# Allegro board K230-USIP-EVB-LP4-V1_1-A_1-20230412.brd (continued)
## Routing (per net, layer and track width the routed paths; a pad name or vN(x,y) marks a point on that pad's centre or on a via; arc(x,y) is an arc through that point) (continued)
GND3: length 4.6
  TOP w0.254: 56.26,30.61 55.73,31.13 U35.1
  TOP w0.305: 56.26,30.61 56.77,30.1 R290.1 R289.1
VBUS_IN: length 1.1
  TOP w0.381: R303.1 70.1,28.83
VDD0V8_KPU_EN: length 4.5
  TOP w0.305: U38.7 60.2,78.23 58.29,80.14 R301.1 C394.1
VDD_0V8: length 10.1
  ART06 w0.305: v1(60.07,35.56) 60.96,36.45 60.96,41.02 v1(59.56,42.42)
  BOTTOM w0.305: v1(60.07,35.56) R267.2 C320.1
VDD_1V1: length 4.4
  TOP w0.381: v1(45.97,28.19) 45.97,25.65
  BOTTOM w0.381: C328.1 R275.1 v1(45.97,28.19)
VDD_1V8: length 84.5
  TOP w0.203: U30.P5 43.16,116.48 v2(42.93,116.71) ; v1(66.57,119.25) 67,118.81 U25.2 ; U30.M4 U30.N4 U30.P3 44.32,116.44 v2(44.32,116.71) ; U34.2 59.11,100.13 v1(58.8,99.82) ; U30.C6 42.66,111.09 v2(42.52,111.23)
  TOP w0.254: U1.R13 25.65,78.38 v2(25.33,78.06) ; v2(32.47,79.36) 32.15,79.68 U1.E11 ; U1.R15 v2(25.33,77.41) ; U1.F13 v2(31.17,78.06) ; U1.H6 v2(30.53,82.61) ; U1.R11 v2(25.33,79.36)
  TOP w0.305: v1(66.19,114.43) R209.1 ; C315.1 v1(58.8,99.82) ; v1(66.57,119.25) C207.1 ; R280.2 v1(44.32,36.32)
  TOP w0.381: R238.1 R239.1 v1(44.58,124.46) ; R241.1 R240.1 v1(45.72,124.46) ; R200.1 v1(7.24,43.18) ; C206.2 4.57,53.21 J12.1 ; R199.1 v1(7.11,45.72) ; R207.1 v1(7.24,38.1) ; R206.1 v1(7.24,40.64) ; v1(49.4,77.09) 49.02,77.09 R129.1 ; R197.1 v1(7.11,50.8) ; R198.1 v1(7.11,48.26) ; J9.1 v1(32.7,119.89)
  BOTTOM w0.254: C258.1 42.04,109.98 C256.1 ; C258.1 41.15,111 R59.2 ; C258.1 42.29,111 v2(42.52,111.23) ; v2(44.32,116.71) R49.2 C257.1 43.18,116.46 v2(42.93,116.71)
  BOTTOM w0.305: R280.2 C323.1 45.21,38.35 47.5,40.64 v1(48.26,40.64) ; C242.2 32.7,120.21 v1(32.7,119.89) ; v1(58.8,99.82) 59.05,99.82 R146.1 ; 38.99,79.5 38.99,80.52 39.5,80.52 40.26,81.28 45.47,81.28 47.62,83.44 49.53,83.44 51.05,84.96 v1(51.05,89.15) ; v1(49.4,77.09) 49.4,82 52.83,85.43 52.83,88.52 v1(53.47,89.15) ; R48.2 C259.1 v1(36.7,109.73)
  BOTTOM w0.381: v1(71.5,50.67) R18.2 R20.2 ; R236.1 R237.1 v1(6.1,83.19) ; v3(41.4,128.27) R234.1 R235.1
  vias: v1(36.58,113.41) v1(36.58,112.14) v1(47.12,43.18) v1(47.12,41.91) v1(48.26,45.72) v1(48.26,44.45) v1(48.26,43.18) v1(48.26,41.91) v1(49.28,45.72) v1(49.28,44.45)
VDD_3V3: length 80.3
  TOP w0.203: U34.1 58.98,100.53 v1(58.8,100.71) ; U30.J10 41.14,113.78 v2(41.16,113.8) U30.K9 ; U36.2 53.01,110.56 v1(52.7,110.87) ; U30.E6 42.66,112.12 v2(42.79,112.25) 42.82,112.28 U30.F5 ; v1(67.71,119.25) 67.4,118.94 U25.1
  TOP w0.254: U1.M7 v2(27.28,82.61) ; U1.E10 v2(32.47,80.66)
  TOP w0.305: C316.2 v1(58.8,100.71) ; R284.2 v1(52.7,105.66) ; J3.57 46.76,128.93 ; v1(52.7,110.87) C367.2 ; v1(67.71,119.25) C208.2 ; J4.6 6.86,91.41 v1(6.6,91.15) 6.85,90.91 J4.5 ; J3.59 47.26,128.92
  TOP w0.381: v1(71.37,116.59) 71.63,116.84 R243.1 R242.1 ; J9.16 v1(32.7,105.79) ; R76.1 32.64,31.11 v1(32.64,25.15) ; R19.1 v1(18.16,18.16) ; TP10.1 v1(19.3,25.4) ; v1(71.75,87) 67.06,87 66.86,87.19 U4.4 ; R11.2 v1(60.96,115.82)
  BOTTOM w0.254: v2(41.16,113.8) 41.15,113.82 C18.1 ; 33.19,80.66 v2(32.47,80.66)
  BOTTOM w0.305: 27.18,85.09 C30.1 C81.1 ; C19.1 C22.1 42.8,112.27 v2(42.79,112.25) ; 35.81,80.14 C83.1 35.81,79.3 36.09,79.02 37.31,79.02 37.64,78.69 39.45,78.69 39.85,79.1 44.04,79.1 47.75,82.8 49.56,82.8 52.32,85.57 v1(52.32,92.33)
  BOTTOM w0.381: C260.1 32.7,105.35 v1(32.7,105.79) ; R190.1 v1(70.99,81.92) ; R245.2 v1(70.99,86.36) ; R194.1 v1(70.99,83.19) R189.1 ; R188.1 v1(70.99,85.09) ; R162.1 v1(70.99,87.63) ; R191.1 v1(71.25,91.44) ; R193.1 v1(70.99,88.9)
  vias: v1(12.32,24.38) v1(12.32,23.11) v1(12.32,21.84) v1(13.59,24.38) v1(13.59,23.11) v1(13.59,21.84) v1(19.3,24.13) v1(19.3,22.99) v1(19.3,21.84) v1(20.57,24.13) v1(20.57,22.99) v1(20.57,21.84) v1(33.15,18.8) v1(33.15,17.65) v1(33.15,16.51) v1(33.15,15.37) v1(34.42,18.8) v1(34.42,17.65) v1(34.42,16.51) v1(34.42,15.37) v1(41.02,25.4) v1(41.02,24.13) v1(41.02,22.86) v1(41.91,33.78) v1(43.43,33.78) v1(47.37,128.78) v1(48.39,128.78) v1(49.4,128.78) v1(50.55,128.78) v1(60.33,20.32) v1(60.33,19.05) v1(61.34,20.32) v1(61.34,19.05) v1(62.36,21.34) v1(62.36,20.32) v1(62.36,19.05) v1(63.5,20.32) v1(63.63,21.34) v1(70.99,110.36) v1(72.26,110.36) v2(38.1,114.43) v2(38.1,113.79)
VDD_5V: length 31.4
  TOP w0.127: 60.71,74.8 60.7,74.81
  TOP w0.254: v1(51.56,29.08) 51.95,29.48 U35.20 ; U35.8 53.46,35.68 v1(53.72,35.94) ; U35.11 51.95,35.55 v1(51.56,35.94) ; v1(53.72,29.21) 53.46,29.48 U35.23
  TOP w0.305: R302.1 v1(45.97,30.23) ; 60.7,74.81 U38.3 ; R23.2 20.3,36.83 ; 57.91,72.52 59.01,72.52 ; R277.1 R289.2 v1(60.96,31.24) ; R301.2 v1(58.57,81.15)
  TOP w0.381: R143.1 v1(31.24,24.77) ; 21.72,17.78 v1(20.7,17.78)
  BOTTOM w0.381: R273.2 R274.2 52.07,24.89 ; 52.07,39.74 52.07,38.99 53.21,38.99 ; v1(45.97,30.23) 45.21,29.46 45.21,27.14 ; v1(58.57,81.15) 59.82,79.91 59.82,73.41
  vias: v1(16.51,37.34) v1(17.53,37.34) v1(18.54,37.34) v1(22.35,19.3) v1(23.62,20.57) v1(23.62,19.3) v1(28.7,26.42) v1(29.72,26.42) v1(30.73,26.42) v1(50.67,28.32) v1(50.8,36.7) v1(54.48,36.7) v1(54.48,28.32) v1(59.18,73.03) v1(59.18,71.75) v1(59.18,70.48) v1(64.9,37.85) v1(64.9,36.83) v1(64.9,35.81) v1(64.9,34.8) v1(64.9,33.78) v1(65.91,36.83) v1(65.91,35.81) v1(65.91,34.8) v1(65.91,33.78)
VDD_5V_O: length 86.6
  TOP w0.305: J3.56 46.26,135.74 ; J4.4 8.88,90.41 ; J3.58 46.76,135.74 ; J3.60 47.26,135.74 ; J4.3 8.88,89.91
  TOP w0.381: R43.2 v1(49.28,87.5) 49.28,88.39 50.78,89.9 v1(55.37,89.9) 56.24,89.03 62.99,89.03 63.37,88.65 v1(63.37,77.98) ; v1(66.42,67.5) U3.5 ; R88.2 v1(62.23,115.82) ; v1(66.42,57.34) U6.5
  BOTTOM w0.381: 64.34,67.69 C16.2 66.23,67.69 v1(66.42,67.5) 67.18,66.74 67.18,65.02 67.4,64.81 67.4,58.32 v1(66.42,57.34) 66.1,57.66 C20.2 64.3,57.66 ; v1(55.37,89.9) 55.37,102.49 53.85,104.01 53.85,109.98 55.88,112.01 55.88,113.28 57.66,115.06 61.47,115.06 v1(62.23,115.82) ; R43.2 v1(49.28,87.5)
  vias: v1(9.14,90.04) v1(9.14,89.03) v1(10.03,89.53) v1(16.13,34.04) v1(16.13,32.89) v1(16.13,31.75) v1(17.4,34.04) v1(17.4,32.89) v1(17.4,31.75) v1(39.88,136.14) v1(40.89,136.14) v1(41.91,136.14) v1(42.93,136.14) v1(67.31,32.26) v1(67.31,30.99) v1(67.31,29.72) v1(67.31,28.45) v1(67.31,27.18)
VDD_CORE_0V8: length 19.5
  TOP w0.254: U1.P9 v2(26.63,81.31) U1.N9 ; U1.P13 v2(25.98,78.71) ; U1.G9 30.85,80.98 v2(30.53,80.66) ; U1.M11 v2(27.93,79.36) ; U1.J12 v2(29.87,78.71) ; U1.P11 v2(25.98,79.36) ; U1.F12 v2(31.17,78.71) ; U1.H12 v2(30.52,78.71) U1.G12 ; U1.K11 v2(29.22,80.01) ; U1.L9 v2(27.93,81.31) U1.M9 ; U1.N11 v2(26.63,79.36) ; U1.L11 v2(28.57,80.01) ; U1.K9 28.9,80.98 v2(29.22,80.66) ; U1.G10 v2(31.17,80.01)
  TOP w0.305: v2(41.02,77.72) 41.78,77.72 41.78,76.96
  TOP w0.381: TP5.1 v1(54.86,72.14) ; TP6.1 v1(56.26,62.87)
  BOTTOM w0.254: v2(39.62,81.41) 39.5,81.53 38.99,81.53 38.99,83.31 ; C38.1 28.32,81.79 27.93,81.39 v2(27.93,81.31) ; C39.1 27.05,81.79 26.63,81.36 v2(26.63,81.31) ; C47.1 26.48,79.5 v2(26.63,79.36)
  BOTTOM w0.305: C37.1 38.1,73.79 v2(38.23,73.66) 38.1,73.53 C36.1 ; v2(40.39,80.37) 40.67,80.64 C43.1 ; C44.1 40.56,79.76 v2(40.39,79.58)
  vias: v1(46.99,66.8) v1(48.26,66.8) v1(48.26,65.53) v1(50.8,65.53) v1(54.1,58.04) v1(54.1,56.9) v1(55.24,64.14) v1(55.24,62.87) v1(55.24,61.59) v1(55.24,60.33) v1(55.24,59.05) v1(55.24,58.04) v1(56.26,64.14) v1(56.26,61.59) v1(56.26,60.33) v1(56.26,59.05) v2(40.39,78.61) v3(44.32,73.15) v3(45.21,73.15) v3(45.21,72.26)
VDD_KPU_0V8: length 5.6
  TOP w0.254: U1.J9 v2(29.87,81.31) U1.H9 ; U1.H8 v2(29.87,81.96) U1.J8 ; U1.J10 v2(29.87,80.66) U1.H10
  TOP w0.381: C49.1 v1(46.1,82.8)
  BOTTOM w0.305: v1(40.89,85.03) 41.08,84.84 41.78,84.84 ; 41.78,83.95 v1(40.89,83.95)
  vias: v1(50.42,88.14) v1(51.69,88.14) v1(53.47,88.14) v1(54.1,55.12) v1(54.48,88.14) v1(54.48,86.87) v1(55.12,53.59) v1(55.12,52.58) v1(55.12,51.31) v1(55.12,50.04) v1(55.12,48.77) v1(55.5,88.14) v1(55.5,86.87) v1(56.13,55.12) v1(56.13,53.59) v1(56.13,52.58) v1(56.13,51.31) v1(56.13,50.04) v1(56.13,48.77) v1(56.52,88.14) v1(56.52,86.87) v1(57.53,88.14) v1(57.53,86.87) v1(58.55,88.14) v1(58.55,86.87) v1(61.59,42.16) v1(61.59,40.89) v1(61.59,39.62) v1(61.59,38.35) v1(62.61,42.16) v1(62.61,40.89) v1(62.61,39.62) v1(62.61,38.35) v1(63.63,42.16) v1(63.63,40.89) v1(63.63,39.62) v1(63.63,38.35)
VDD_PA: length 20.6
  TOP w0.254: U16.13 58.42,124.97 v1(59.31,125.86) ; U16.9 61.08,123.06 61.47,123.44 v1(61.47,124.21) C308.1 ; U16.3 v1(58.42,119.38)
  TOP w0.381: v1(58.42,119.38) C7.1 C303.1 R11.1 R88.1
  ART03 w0.508: v1(58.42,119.38) 61.47,122.43 v1(61.47,124.21) 59.82,125.86 v1(59.31,125.86)
  BOTTOM w0.381: C304.1 v1(59.31,125.86)
3D_CTRL_IN: length 81.1
  TOP w0.127: J3.49 44.76,131.39 44.32,131.83 v3(43.94,131.83) ; R83.1 v1(6.22,77.34)
  ART06 w0.127: v3(43.94,131.83) 43.69,132.08 42.74,132.08 40.32,129.67 33.27,129.67 21.21,117.6 21.21,93.34 13.21,85.34 8.51,85.34 7.51,84.34 7.51,78.63 v1(6.22,77.34)
3D_CTRL_OUT1: length 87.2
  TOP w0.127: v3(42.82,131.6) 43,131.42 43.97,131.42 44.26,131.13 J3.47 ; v1(6.22,70.1) 6.6,70.48 R85.1
  ART06 w0.127: v3(42.82,131.6) 40.51,129.29 33.4,129.29 21.59,117.47 21.59,93.12 13.46,84.99 8.66,84.99 7.79,84.11 7.79,71.67 v1(6.22,70.1)
3D_CTRL_OUT2: length 87.5
  TOP w0.127: v3(43.76,132.59) J3.46 ; R87.1 6.35,78.49 4.83,80.01 v1(3.56,80.01)
  ART06 w0.127: v3(43.76,132.59) 43.25,133.1 32.44,133.1 18.03,118.69 18.03,96.41 9.89,88.27 6.22,88.27 1.02,83.06 1.02,80.64 1.65,80.01 v1(3.56,80.01)
ACRC: length 4
  TOP w0.127: 56.13,117.98 57.15,117.98 57.15,118.62 56.77,119 56.77,119.38 57.42,120.03 U16.1
ADC_0: length 62.7
  TOP w0.127: R25.1 52.96,94.36 52.96,100.46 v1(52.45,100.97) ; R51.1 v1(48.01,123.32)
  ART06 w0.127: v1(52.45,100.97) 51.82,100.33 50.8,100.33 46.61,104.52 46.61,121.92 v1(48.01,123.32)
  BOTTOM w0.127: J15.1 45.09,135.89 47.12,135.89 49.91,133.1 49.91,127 48.01,125.09 v1(48.01,123.32)
ADC_1: length 57.1
  TOP w0.127: v1(49.66,123.32) 50.04,123.32 51.44,124.71 R52.1 ; v1(51.42,100.95) 50.71,100.24 50.71,94.4 R26.1
  ART06 w0.127: v1(49.66,123.32) 46.99,120.65 46.99,104.78 50.82,100.95 v1(51.42,100.95)
  BOTTOM w0.127: v1(49.66,123.32) 49.66,125.22 51.18,126.75 51.18,132.33 J15.2
ADC_2: length 63.6
  TOP w0.127: J15.3 49.15,136.91 49.15,132.84 v1(47.88,131.57) 46.3,131.57 45.26,132.62 J3.52 ; v1(53.47,100.97) 53.25,100.75 53.25,94.02 49.02,89.79 49.02,89.28 R27.1
  ART06 w0.127: v1(47.88,131.57) 47.88,127.84 50.8,124.92 50.8,122.68 47.62,119.51 47.62,104.65 50.67,101.6 52.83,101.6 v1(53.47,100.97)
ADC_3: length 49.6
  TOP w0.127: R28.1 48.9,94.36 50.15,95.62 v1(50.15,103.5)
  ART06 w0.127: J15.4 53.85,134.75 53.85,119.63 48.39,114.17 48.39,105.27 v1(50.15,103.5)
ADC_4: length 54.6
  TOP w0.127: v1(52.32,102.36) 51.94,101.98 51.94,100.46 52.68,99.72 52.68,95.22 R29.1
  ART06 w0.127: v1(52.32,102.36) 51.69,103 50.93,103 50.67,103.25 50.67,103.76 48.77,105.66 48.77,113.92 54.23,119.38 54.23,136.91 J15.5
ADC_5: length 81.3
  TOP w0.127: R30.1 50.43,95.26 50.43,102.76 v1(51.18,103.5)
  ART06 w0.127: 55.24,138.43 59.05,134.62 71.5,134.62 74.93,131.2 v1(74.93,121.28) 71.37,117.73 64.64,117.73 63.25,116.33 56.13,116.33 50.29,110.49 50.29,105.03 51.18,104.14 v1(51.18,103.5)
  BOTTOM w0.127: R221.1 v1(74.93,121.28)
BOOT0: length 63.3
  TOP w0.127: SW1.1 70.48,52.2 70.99,51.69 v1(71.5,51.69) ; U1.C8 v2(33.77,81.31)
  ART06 w0.127: v1(71.5,51.69) 71.5,53.34 68.47,56.38 68.47,59.3 66.93,60.83 65.66,60.83 64.14,62.36 64.14,71.37 63.12,72.39 61.98,72.39 56.26,78.11 50.29,78.11 48.64,79.76 41.55,79.76 40.54,80.77 39.12,80.77 38.84,81.05 34.03,81.05 v2(33.77,81.31)
  BOTTOM w0.127: v1(71.5,51.69) R18.1 TVS4.1
BOOT1: length 59.4
  TOP w0.127: v2(33.12,81.31) 33.13,81.31 U1.C9 ; 67.94,53.66 67.94,55.12 v1(68.07,55.24)
  ART06 w0.127: v1(68.07,55.24) 68.07,59.18 66.8,60.45 65.53,60.45 63.75,62.23 63.75,70.61 63.25,71.12 62.61,71.12 56.01,77.72 50.16,77.72 48.49,79.4 41.25,79.4 40.68,79.97 39.79,79.97 39.37,80.39 38.61,80.39 38.21,80.78 33.65,80.78 v2(33.12,81.31)
  BOTTOM w0.127: v1(68.07,55.24) 68.07,53.09 68.33,52.83 TVS5.1 R20.1
CA_A0: length 39.1
  TOP w0.086: v2(19.02,54.03) 18.95,54.03 U5.H2 ; U1.M19 27.28,74.81 v2(27.28,75.46)
  ART03 w0.086: v2(27.28,75.46) 27.28,74.9 26.86,74.49 25.62,74.49 25,73.87 25,73.31 24.69,73 24.69,72.06 24.55,71.92 23.03,71.92 22.89,71.78 22.89,71.58 23.03,71.44 24.55,71.44 24.69,71.3 24.69,71.1 24.55,70.96 23.03,70.96 22.89,70.82 22.89,70.62 23.03,70.48 24.55,70.48 24.69,70.34 24.69,70.04 24.6,69.95 23,69.95 22.89,69.84 22.89,63.83 22.42,63.36 22.42,63.16 22.69,62.89 22.69,62.69 22.55,62.55 22.35,62.55 22.08,62.82 21.88,62.82 21.74,62.68 21.74,62.49 22.01,62.21 22.01,62.02 21.87,61.87 21.67,61.87 21.4,62.15 21.2,62.15 21.06,62 21.06,61.81 21.36,61.5 21.36,61.09 20.22,59.95 20.22,59.39 20.37,59.25 20.69,59.25 20.83,59.11 20.83,58.91 20.69,58.77 20.37,58.77 20.22,58.63 20.22,58.43 20.37,58.29 20.69,58.29 20.83,58.15 20.83,57.95 20.69,57.81 20.37,57.81 20.22,57.67 20.22,54.51 20.07,54.36 19.35,54.36 v2(19.02,54.03)
CA_A1: length 41.5
  TOP w0.086: v2(19.02,53.38) 18.7,53.06 U5.J2 ; U1.L16 v2(27.93,76.11)
  ART03 w0.086: v2(27.93,76.11) 27.6,75.79 27.09,75.79 26.95,75.64 26.95,75.22 26.86,75.13 25.6,75.13 24.96,74.49 24.5,74.49 24.35,74.34 24.35,73.27 24.21,73.13 24.21,72.45 24.09,72.34 23.84,72.34 23.75,72.43 23.75,73.25 23.62,73.38 22.63,73.38 22.53,73.28 22.53,64.01 20.52,62 20.52,61.8 20.92,61.41 20.92,61.21 20.78,61.07 20.58,61.07 20.18,61.46 19.99,61.46 19.85,61.32 19.85,61.12 20.24,60.73 20.24,60.53 20.1,60.39 19.9,60.39 19.51,60.78 19.31,60.78 19.07,60.55 19.07,60.35 19.65,59.77 19.65,59.63 19.46,59.43 19.31,59.43 18.73,60.01 18.53,60.01 18.26,59.74 18.26,59.03 18.4,58.89 19.29,58.89 19.43,58.75 19.43,58.55 19.29,58.41 18.37,58.41 18.29,58.32 18.29,58.02 18.37,57.93 19.29,57.93 19.43,57.79 19.43,57.59 19.29,57.45 18.77,57.45 18.62,57.31 18.62,57.08 18.77,56.94 19.26,56.94 19.41,56.8 19.41,56.6 19.26,56.46 18.77,56.46 18.62,56.32 18.62,53.79 v2(19.02,53.38)
CA_A2: length 39.3
  TOP w0.086: U1.N19 v2(27.28,74.16) ; U5.H9 24.3,53.71 v2(24.63,53.38)
  ART03 w0.086: v2(27.28,74.16) 27.07,74.16 26.95,74.04 26.95,61.93 27.09,61.79 27.32,61.79 27.46,61.65 27.46,61.45 27.32,61.31 27.09,61.31 26.95,61.17 26.95,60.97 27.09,60.83 27.32,60.83 27.46,60.69 27.46,60.49 27.32,60.35 27.07,60.35 26.92,60.21 26.92,60.01 27.07,59.87 27.32,59.87 27.46,59.73 27.46,59.53 27.32,59.39 27.07,59.39 26.92,59.25 26.92,58.88 27.05,58.75 27.33,58.75 27.43,58.65 27.43,58.22 27.3,58.09 26.57,58.09 26.44,58.22 26.44,60.1 26.31,60.22 26.08,60.22 25.94,60.08 25.94,58.36 25.8,58.22 25.6,58.22 25.46,58.36 25.46,60.08 25.32,60.22 25.09,60.22 24.95,60.08 24.95,59.07 24.81,58.93 24.61,58.93 24.47,59.07 24.47,60.08 24.33,60.22 23.93,60.22 23.67,59.97 23.67,59.28 24.23,58.72 24.23,56.49 24.41,56.31 24.89,56.31 25.03,56.18 25.03,53.47 24.94,53.38 v2(24.63,53.38)
CA_A3: length 38.8
  TOP w0.086: U1.N20 v2(27.28,73.51) ; v2(25.43,53.38) 25.1,53.71 U5.H10
  ART03 w0.086: v2(27.28,73.51) 27.48,73.3 27.48,72.39 27.31,72.22 27.31,71.87 27.45,71.73 27.67,71.73 27.81,71.59 27.81,71.39 27.67,71.25 27.45,71.25 27.31,71.11 27.31,70.91 27.45,70.77 27.67,70.77 27.81,70.63 27.81,70.43 27.67,70.29 27.45,70.29 27.31,70.15 27.31,69.95 27.45,69.81 27.67,69.81 27.81,69.67 27.81,69.47 27.67,69.33 27.45,69.33 27.31,69.19 27.31,68.99 27.45,68.85 27.67,68.85 27.81,68.71 27.81,68.51 27.67,68.37 27.45,68.37 27.31,68.23 27.31,68.03 27.45,67.89 27.67,67.89 27.81,67.75 27.81,67.55 27.67,67.41 27.45,67.41 27.31,67.27 27.31,67.07 27.45,66.93 27.67,66.93 27.81,66.79 27.81,66.59 27.67,66.45 27.45,66.45 27.31,66.31 27.31,66.11 27.45,65.97 27.67,65.97 27.81,65.83 27.81,65.63 27.67,65.49 27.45,65.49 27.31,65.35 27.31,65.15 27.45,65.01 27.67,65.01 27.81,64.87 27.81,64.67 27.67,64.53 27.45,64.53 27.31,64.39 27.31,64.19 27.45,64.05 27.67,64.05 27.81,63.91 27.81,63.71 27.67,63.57 27.45,63.57 27.31,63.43 27.31,63.23 27.45,63.09 27.67,63.09 27.81,62.95 27.81,62.75 27.67,62.61 27.45,62.61 27.31,62.47 27.31,62.27 27.45,62.13 27.67,62.13 27.81,61.99 27.81,57.73 27.69,57.61 25.94,57.61 25.83,57.5 25.83,55.7 25.97,55.56 26.5,55.56 26.64,55.42 26.64,55.22 26.5,55.08 25.97,55.08 25.83,54.94 25.83,53.8 25.92,53.71 26.56,53.71 26.64,53.62 26.64,50.61 26.56,50.52 25.92,50.52 25.83,50.61 25.83,52.98 v2(25.43,53.38)
CA_A4: length 39.6
  TOP w0.086: v2(26.23,54.03) 25.9,53.71 U5.H11 ; U1.M18 v2(27.93,75.46)
  ART03 w0.086: v2(27.93,75.46) 27.93,72.25 28.17,72.01 28.17,57.3 28.03,57.16 27.55,57.16 27.41,57.02 27.41,56.82 27.55,56.68 28.03,56.68 28.17,56.54 28.17,56.34 28.03,56.2 27.55,56.2 27.41,56.06 27.41,55.86 27.55,55.72 28.03,55.72 28.17,55.58 28.17,55.38 28.03,55.24 27.55,55.24 27.41,55.1 27.41,54.9 27.55,54.76 28.03,54.76 28.17,54.62 28.17,49.46 28.08,49.38 27.77,49.38 27.69,49.46 27.69,50.73 27.55,50.87 27.19,50.87 27.05,51.01 27.05,51.21 27.19,51.35 27.55,51.35 27.69,51.49 27.69,51.69 27.55,51.83 27.19,51.83 27.05,51.97 27.05,52.17 27.19,52.31 27.55,52.31 27.69,52.45 27.69,52.69 27.55,52.83 27.42,52.83 27.28,52.97 27.28,53.17 27.42,53.31 27.55,53.31 27.69,53.45 27.69,53.95 27.6,54.03 v2(26.23,54.03)
CA_A5: length 37.9
  TOP w0.086: v2(25.43,52.73) 25.5,52.73 U5.J11 ; U1.P19 v2(26.63,74.16)
  ART03 w0.086: v2(25.43,52.73) 25.05,52.73 24.97,52.65 24.97,50.56 24.88,50.47 22.43,50.47 22.24,50.66 22.24,51.61 22.38,51.74 22.63,51.74 22.76,51.61 22.76,51.08 22.85,50.98 23.14,50.98 23.24,51.08 23.24,51.48 23.38,51.63 23.58,51.63 23.72,51.48 23.72,51.12 23.86,50.98 24.14,50.98 24.23,51.07 24.23,55.66 24.09,55.79 23.71,55.79 23.32,56.18 23.32,60.12 23.77,60.58 26.49,60.58 26.59,60.68 26.59,72.98 26.31,73.26 26.31,73.84 v2(26.63,74.16)
CA_B0: length 38.3
  TOP w0.086: U7.H2 31.65,54.03 v2(31.72,54.03) ; U1.E20 v2(31.82,73.51)
  ART03 w0.086: v2(31.72,54.03) 32.17,54.48 33.4,54.48 33.78,54.1 33.78,53.21 34.52,52.48 34.52,51.44 34.67,51.28 35.17,51.28 35.31,51.42 35.31,52.34 35.45,52.48 35.65,52.48 35.79,52.34 35.79,51.37 35.96,51.21 36.8,51.21 36.93,51.33 36.93,54.9 36.81,55.01 36.3,55.01 36.12,55.19 36.12,58.29 35.59,58.82 35.59,63.77 35.47,63.88 34.17,63.88 34.09,63.97 34.09,64.97 34.23,65.11 35.42,65.11 35.59,65.27 35.59,68.43 31.82,72.19 v2(31.82,73.51)
CA_B1: length 39.6
  TOP w0.086: v2(30.92,54.03) 30.92,53.46 U7.J2 ; U1.G19 v2(30.52,74.16)
  ART03 w0.086: v2(30.52,74.16) 30.2,73.84 30.2,69.32 30.32,69.19 31.51,69.19 31.65,69.05 31.65,68.86 31.51,68.71 31.16,68.71 31.02,68.57 31.02,68.38 31.16,68.23 31.74,68.23 31.88,68.09 31.88,67.89 31.74,67.75 31.03,67.75 30.89,67.61 30.89,67.41 31.03,67.27 31.74,67.27 31.88,67.13 31.88,66.93 31.74,66.79 31.03,66.79 30.89,66.65 30.89,66.45 31.03,66.31 31.74,66.31 31.88,66.17 31.88,65.97 31.74,65.83 31.03,65.83 30.89,65.69 30.89,65.49 31.03,65.35 31.74,65.35 31.88,65.21 31.88,65.01 31.74,64.87 31.03,64.87 30.89,64.73 30.89,64.53 31.03,64.39 31.74,64.39 31.88,64.25 31.88,64.05 31.74,63.91 31.03,63.91 30.89,63.77 30.89,63.57 31.03,63.43 31.74,63.43 31.88,63.29 31.88,63.09 31.74,62.95 31.03,62.95 30.89,62.81 30.89,62.61 31.03,62.47 31.74,62.47 31.88,62.33 31.88,62.13 31.74,61.99 31.03,61.99 30.89,61.85 30.89,61.65 31.03,61.51 31.74,61.51 31.88,61.37 31.88,61.17 31.74,61.03 31.03,61.03 30.89,60.89 30.89,60.69 31.03,60.55 31.74,60.55 31.88,60.41 31.88,60.21 31.74,60.07 31.03,60.07 30.89,59.93 30.89,59.73 31.03,59.59 31.74,59.59 31.88,59.45 31.88,59.25 31.74,59.11 31.43,59.11 31.34,59.03 31.34,54.45 v2(30.92,54.03)
CA_B2: length 40
  TOP w0.086: U1.G18 v2(31.18,74.81) ; U7.H9 37,53.71 v2(37.33,53.38)
  ART03 w0.086: v2(31.18,74.81) 30.86,74.5 30.86,74.3 30.86,74.29 30.86,74.03 31.04,73.84 31.05,73.84 31.07,73.83 31.31,73.83 31.31,73.83 31.96,73.83 31.96,73.83 31.97,73.83 32.14,73.65 32.14,72.38 35.94,68.58 35.94,64.89 35.8,64.74 34.58,64.74 34.44,64.6 34.44,64.41 34.58,64.26 35.8,64.26 35.94,64.12 35.94,61.17 36.08,61.03 37.68,61.03 37.8,60.92 37.8,60.66 37.68,60.55 36.08,60.55 35.94,60.41 35.94,60.21 36.08,60.07 37.68,60.07 37.82,59.93 37.82,59.73 37.68,59.59 36.08,59.59 35.94,59.45 35.94,59.13 36.12,58.95 37.65,58.95 37.73,58.88 37.73,58.35 37.58,58.21 36.67,58.21 36.53,58.07 36.53,57.87 36.67,57.73 37.58,57.73 37.73,57.59 37.73,57.39 37.58,57.25 37,57.25 36.86,57.11 36.86,56.91 37,56.77 37.58,56.77 37.73,56.62 37.73,53.79 v2(37.33,53.38)
CA_B3: length 40.6
  TOP w0.086: v2(30.52,74.81) 30.52,75.46 U1.H17 ; U7.H10 37.8,53.71 v2(38.13,53.38)
  ART03 w0.086: v2(38.13,53.38) 37.73,52.99 37.73,49.9 37.65,49.81 35.3,49.81 35.16,49.95 35.16,50.79 35.07,50.88 34.77,50.88 34.68,50.79 34.68,49.69 34.59,49.61 33.83,49.61 33.68,49.76 33.68,52.43 32.89,53.21 32.89,53.47 32.65,53.71 30.62,53.71 30.53,53.8 30.53,68.5 30.41,68.62 29.94,68.62 29.84,68.72 29.84,73 29.55,73.29 29.55,74.49 29.87,74.81 v2(30.52,74.81)
CA_B4: length 40.9
  TOP w0.086: U7.H11 38.6,53.71 v2(38.93,54.03) ; U1.F17 v2(31.18,75.46)
  ART03 w0.086: v2(38.93,54.03) 39.32,53.64 39.32,51.7 39.18,51.56 38.47,51.56 38.33,51.42 38.33,51.22 38.47,51.08 39.18,51.08 39.32,50.94 39.32,50.63 39.23,50.55 38.29,50.55 38.2,50.46 38.2,49.92 38.32,49.81 40.05,49.81 40.16,49.92 40.16,55.51 40.02,55.66 39.43,55.66 39.29,55.8 39.29,55.99 39.43,56.14 40.02,56.14 40.16,56.28 40.16,60.43 36.7,63.88 36.7,69.42 32.89,73.23 32.89,73.94 32.81,74.03 32.81,74.03 32.26,74.58 32.26,74.82 32.14,74.93 32.14,74.94 31.96,75.13 31.95,75.13 31.94,75.13 31.5,75.13 v2(31.18,75.46)
CA_B5: length 39.2
  TOP w0.086: U7.J11 38.6,53.06 v2(38.93,52.73) ; U1.F19 v2(31.18,74.16)
  ART03 w0.086: v2(31.18,74.16) 31.49,74.47 31.69,74.47 31.69,74.48 31.96,74.48 32.14,74.29 32.14,74.28 32.51,73.92 32.51,73.1 34.78,70.84 34.78,70.64 34.68,70.54 34.68,70.35 34.82,70.2 35.02,70.2 35.12,70.3 35.32,70.3 35.46,70.16 35.46,69.96 35.36,69.87 35.36,69.67 35.5,69.53 35.7,69.53 35.8,69.62 35.99,69.62 36.14,69.48 36.14,69.28 36.04,69.19 36.04,68.99 36.32,68.71 36.32,63.53 36.46,63.39 36.69,63.39 36.83,63.25 36.83,63.05 36.69,62.91 36.46,62.91 36.32,62.77 36.32,62.57 36.46,62.43 37.65,62.43 37.8,62.29 37.8,62.09 37.65,61.95 36.46,61.95 36.32,61.81 36.32,61.48 36.41,61.39 38.08,61.39 38.17,61.31 38.17,60.89 38.3,60.76 39.31,60.76 39.45,60.62 39.45,60.42 39.31,60.28 38.31,60.28 38.2,60.16 38.2,59.97 38.36,59.8 39.66,59.8 39.8,59.66 39.8,59.46 39.66,59.32 38.41,59.32 38.27,59.18 38.27,58.98 38.41,58.84 39.66,58.84 39.8,58.7 39.8,58.5 39.66,58.36 38.67,58.36 38.53,58.22 38.53,53.14 v2(38.93,52.73)
CC1: length 6.6
  TOP w0.127: J2.B5 73.45,15.7 73.91,15.24 v1(73.91,13.46) 73.91,13.08 73.53,12.7 J2.A5
  BOTTOM w0.127: R9.1 v1(73.91,13.46)
CC_T: length 12.5
  TOP w0.127: J6.A5 73.32,102.91 74.17,103.76 74.17,105.03 73.29,105.91 J6.B5 71.08,105.91 68.45,108.54 R195.1
CK_C_A: length 37.6
  TOP w0.089: U5.J9 23.9,52.73 v2(23.83,52.73) ; U1.R20 v2(25.98,73.51)
  ART03 w0.089: v2(25.98,73.51) 26,73.49 26,68.91 25.64,68.55 24.37,68.55 24.22,68.4 24.22,68.17 24.37,68.02 25.64,68.02 26,67.67 26,67.15 25.64,66.8 24.37,66.8 24.22,66.65 24.22,66.42 24.37,66.27 25.64,66.27 26,65.91 26,65.4 25.64,65.05 24.37,65.05 24.22,64.9 24.22,64.67 24.37,64.51 25.64,64.51 26,64.16 26,63.65 25.64,63.3 24.37,63.3 24.22,63.14 24.22,62.91 24.37,62.76 25.64,62.76 26,62.41 26,61.55 25.62,61.18 23.08,61.18 22.68,60.78 22.68,54.56 23.37,53.87 23.37,53.67 23.47,53.57 23.62,53.57 23.72,53.46 23.72,53.26 23.62,53.16 23.47,53.16 23.37,53.05 23.37,52.83 23.47,52.73 v2(23.83,52.73)
CK_C_B: length 38.3
  TOP w0.089: U1.F20 v2(31.18,73.51) ; v2(36.53,53.38) 36.85,53.06 U7.J9
  ART03 w0.089: v2(36.53,53.38) 36.2,53.71 35.54,53.71 35.01,54.24 35.01,59.19 34.54,59.66 32.91,59.66 32.82,59.75 32.82,60.16 32.97,60.31 34.62,60.31 34.98,60.66 34.98,61.17 34.62,61.53 32.97,61.53 32.82,61.68 32.82,61.91 32.97,62.06 34.62,62.06 34.98,62.41 34.98,62.93 34.62,63.28 32.97,63.28 32.82,63.43 32.82,65.59 32.97,65.74 34.6,65.74 34.95,66.09 34.95,68.05 34.61,68.39 34.1,68.39 33.73,68.02 33.73,67.11 33.6,66.98 33.1,66.98 32.94,67.14 32.94,69.75 31.83,70.87 31.83,71.32 31.08,72.07 31.08,73.41 v2(31.18,73.51)
CK_T_A: length 37.6
  TOP w0.089: v2(23.03,52.73) 23.1,52.73 U5.J8 ; U1.R19 v2(25.98,74.16)
  ART03 w0.089: v2(23.03,52.73) 23.03,53.73 22.34,54.42 22.34,60.92 22.93,61.52 25.48,61.52 25.65,61.7 25.65,62.27 25.5,62.42 24.23,62.42 23.88,62.77 23.88,63.28 24.23,63.64 25.5,63.64 25.65,63.79 25.65,64.02 25.5,64.17 24.23,64.17 23.88,64.52 23.88,65.04 24.23,65.39 25.5,65.39 25.65,65.54 25.65,65.77 25.5,65.92 24.23,65.92 23.88,66.28 23.88,66.79 24.23,67.14 25.5,67.14 25.65,67.3 25.65,67.52 25.5,67.68 24.23,67.68 23.88,68.03 23.88,68.54 24.23,68.9 25.5,68.9 25.65,69.05 25.65,73.84 v2(25.98,74.16)
CK_T_B: length 38.4
  TOP w0.089: v2(35.73,53.38) 36.05,53.06 U7.J8 ; U1.G20 v2(30.53,73.51)
  ART03 w0.089: v2(35.73,53.38) 35.71,53.37 35.4,53.37 35.19,53.58 35.04,53.58 34.97,53.52 34.83,53.52 34.72,53.62 34.72,53.77 34.79,53.84 34.79,53.98 34.67,54.1 34.67,59.05 34.4,59.32 32.76,59.32 32.47,59.61 32.47,60.3 32.83,60.65 34.48,60.65 34.63,60.8 34.63,61.03 34.48,61.18 32.83,61.18 32.47,61.54 32.47,62.05 32.83,62.4 34.48,62.4 34.63,62.56 34.63,62.78 34.48,62.94 32.83,62.94 32.47,63.29 32.47,65.73 32.83,66.08 34.46,66.08 34.61,66.23 34.61,67.9 34.47,68.05 34.24,68.05 34.07,67.88 34.07,66.97 33.75,66.64 32.95,66.64 32.6,66.99 32.6,69.61 31.48,70.72 31.48,71.18 30.73,71.93 30.73,73.38 30.6,73.51 v2(30.53,73.51)
CKE_A: length 39.9
  TOP w0.086: v2(19.82,53.38) 20.15,53.06 U5.J4 ; U1.N17 v2(26.63,76.11)
  ART03 w0.086: v2(26.63,76.11) 26.3,75.79 25.49,75.79 24.84,75.14 23.84,75.14 23.7,74.99 23.7,73.97 23.55,73.81 22.18,73.81 22.1,73.73 22.1,64.14 17.82,59.86 17.82,51.75 17.97,51.61 18.76,51.61 18.9,51.47 18.9,51.27 18.76,51.13 17.97,51.13 17.82,50.99 17.82,49.9 17.91,49.81 19.4,49.81 19.48,49.9 19.48,53.04 v2(19.82,53.38)
CKE_B: length 41
  TOP w0.086: U1.J18 v2(29.22,74.81) ; v2(32.52,52.73) 32.85,53.06 U7.J4
  ART03 w0.086: v2(32.52,52.73) 32.76,52.73 32.89,52.6 32.89,50.66 32.78,50.55 32.4,50.55 32.29,50.66 32.29,51.6 32.15,51.74 31.95,51.74 31.81,51.6 31.81,49.7 31.69,49.58 31.44,49.58 31.33,49.7 31.33,51.6 31.19,51.74 30.99,51.74 30.85,51.6 30.85,50.61 30.71,50.47 30.51,50.47 30.37,50.61 30.37,51.57 30.23,51.71 30.03,51.71 29.89,51.57 29.89,50.61 29.75,50.47 29.26,50.47 29.13,50.6 29.13,58.33 29.27,58.47 29.68,58.47 29.82,58.61 29.82,58.81 29.68,58.95 29.27,58.95 29.13,59.09 29.13,72.52 28.9,72.75 28.9,74.49 v2(29.22,74.81)
CS_A: length 37.9
  TOP w0.086: U1.T20 v2(25.33,73.51) ; v2(19.82,54.03) 20.15,53.71 U5.H4
  ART03 w0.086: v2(19.82,54.03) 20.22,53.64 20.22,49.9 20.33,49.79 21.66,49.79 21.74,49.87 21.74,50.34 21.6,50.48 21.17,50.48 21.02,50.62 21.02,50.82 21.17,50.96 21.55,50.96 21.69,51.1 21.69,51.3 21.55,51.44 21.17,51.44 21.02,51.58 21.02,52.28 21.17,52.42 21.98,52.42 22.12,52.57 22.12,52.76 21.98,52.9 21.17,52.9 21.02,53.05 21.02,56.86 21.74,57.58 21.74,59.04 21.6,59.18 21.4,59.18 21.26,59.32 21.26,59.52 21.4,59.66 21.6,59.66 21.74,59.8 21.74,60 21.6,60.14 21.4,60.14 21.26,60.28 21.26,60.48 21.4,60.62 21.6,60.62 21.74,60.76 21.74,61.21 23.27,62.74 23.27,69.44 23.41,69.58 24.9,69.58 25.04,69.72 25.04,72.85 25.33,73.13 v2(25.33,73.51)
CS_B: length 38.8
  TOP w0.086: U7.H4 32.85,53.71 v2(32.52,53.38) ; U1.J20 v2(29.23,74.16)
  ART03 w0.086: v2(29.23,74.16) 29.23,73.06 29.49,72.8 29.49,68.35 29.58,68.26 30.06,68.26 30.18,68.15 30.18,67.9 30.03,67.76 29.63,67.76 29.49,67.62 29.49,67.42 29.63,67.28 30.03,67.28 30.18,67.14 30.18,66.94 30.03,66.8 29.63,66.8 29.49,66.66 29.49,66.46 29.63,66.32 30.03,66.32 30.18,66.18 30.18,65.98 30.03,65.84 29.63,65.84 29.49,65.7 29.49,65.5 29.63,65.36 30.03,65.36 30.18,65.22 30.18,65.02 30.03,64.88 29.63,64.88 29.49,64.74 29.49,64.54 29.63,64.4 30.03,64.4 30.18,64.26 30.18,64.06 30.03,63.92 29.63,63.92 29.49,63.78 29.49,63.58 29.63,63.44 30.03,63.44 30.18,63.3 30.18,63.1 30.03,62.96 29.63,62.96 29.49,62.82 29.49,62.62 29.63,62.48 30.03,62.48 30.18,62.34 30.18,62.14 30.03,62 29.63,62 29.49,61.86 29.49,61.66 29.63,61.52 30.03,61.52 30.18,61.38 30.18,61.18 30.03,61.04 29.63,61.04 29.49,60.9 29.49,60.7 29.63,60.56 30.03,60.56 30.18,60.42 30.18,60.22 30.03,60.08 29.63,60.08 29.49,59.94 29.49,59.74 29.63,59.6 30.03,59.6 30.18,59.46 30.18,57.78 30.07,57.68 29.61,57.68 29.51,57.58 29.51,55.72 29.66,55.58 30.03,55.58 30.18,55.44 30.18,55.24 30.03,55.1 29.66,55.1 29.51,54.96 29.51,52.55 29.65,52.41 29.91,52.41 30.06,52.55 30.06,52.84 30.2,52.98 30.39,52.98 30.54,52.84 30.54,52.55 30.68,52.41 31.23,52.41 31.32,52.5 31.32,52.86 31.52,53.06 32.31,53.06 32.52,53.28 v2(32.52,53.38)
DDR_1V8: length 8.6
  TOP w0.254: v2(19.82,48.18) 20.15,48.51 U5.T4 ; v2(32.52,48.18) 32.85,48.51 U7.T4 ; v2(38.93,48.19) 39,48.19 U7.U12 ; U5.F1 17.9,55.01 v2(18.22,54.68) ; U5.T9 24.15,48.51 v2(23.83,48.83) ; v2(17.42,47.53) 17.75,47.86 U5.U1 ; U7.T9 36.85,48.51 v2(36.53,48.83) ; v2(30.12,47.53) 30.45,47.86 U7.U1 ; U7.F1 30.45,55.01 v2(30.12,54.68) ; v2(33.32,54.03) 33,54.36 U7.G4 ; U5.U12 26.95,48.18 v2(27.03,48.18) ; U7.G9 36.6,54.03 v2(36.53,54.03) ; U7.F12 39.4,55.01 v2(39.73,54.68) ; U5.F12 26.7,55.01 v2(27.03,54.68) ; U5.G9 24.3,54.36 v2(24.63,54.03) ; v2(19.82,54.68) 20.15,54.36 U5.G4
  vias: v1(44.07,54.36) v1(44.7,53.21) v1(45.72,53.21) v2(22.9,48.83) v2(22.9,48.18) v2(35.73,48.83) v2(35.73,48.18) v3(29.08,50.04) v3(29.08,48.77)
DDR_CORE_0V8: length 3.2
  TOP w0.254: U1.N13 v2(26.63,78.06) ; U1.L13 v2(28.58,78.71) U1.K13 ; U1.M13 v2(27.28,78.06)
  BOTTOM w0.254: C66.1 21.46,76.09 21.06,76.49 v2(21.06,76.75) 21.27,76.96 C65.1
  vias: v1(46.99,69.47) v1(46.99,68.45) v1(48.26,69.47) v1(48.26,68.45)
DDR_VAA_1V8: length 2.5
  TOP w0.254: U1.K15 v2(29.22,76.76)
  BOTTOM w0.254: C77.1 29.28,76.71 v2(29.22,76.76)
  BOTTOM w0.381: C269.1 33.91,73.28 C76.1
  vias: v1(44.2,50.55) v1(44.7,49.28) v1(45.85,50.16) v1(45.85,49.28) v2(33.77,73.51)
DDR_VDDQ_1V1: length 55.4
  TOP w0.254: v2(33.32,53.38) 33.65,53.71 U7.H5 ; U5.B8 23.5,57.61 v2(23.83,57.93) ; U5.R12 26.7,49.16 v2(27.03,48.83) ; U1.L14 v2(27.93,77.41) ; U5.W5 21.35,46.88 v2(21.42,46.88) ; v2(17.42,56.63) 17.75,56.31 U5.D1 ; v2(23.83,44.93) 23.5,45.26 U5.AA8 ; U7.U5 34.05,47.53 v2(34.12,47.53) ; v2(36.53,44.93) 36.2,45.26 U7.AA8 ; v2(21.42,55.98) 21.35,55.98 U5.D5 ; U5.D12 26.7,56.31 v2(27.03,56.63) ; v2(39.73,46.23) 39.4,46.56 U7.W12 ; v2(20.62,48.83) 20.95,49.16 U5.R5 ; v2(20.62,44.93) 20.95,45.26 U5.AA5 ; U7.R5 33.65,49.16 v2(33.32,48.83) ; U7.F10 37.8,55.01 v2(38.13,55.33) ; U5.F8 23.35,55.01 v2(23.03,54.69) ; U5.U3 19.35,47.86 v2(19.02,47.53) ; v2(32.52,52.08) 32.45,52.08 U7.K3 ; U7.A9 36.6,58.58 v2(36.53,58.58) ; U5.H5 21.35,53.38 v2(21.42,53.38) ; U7.F3 32.05,55.01 v2(31.72,55.33) ; U7.B5 34.05,57.93 v2(34.12,57.93) ; U5.F5 21.35,54.68 v2(21.42,54.68) ; v2(27.03,52.73) 26.7,52.41 U5.K12 ; U7.U10 37.8,47.86 v2(38.13,47.53) ; U7.F5 33.8,55.01 v2(34.12,55.33) ; U5.H8 23.5,53.71 v2(23.83,54.03) ; v2(30.12,52.08) 30.2,52.08 U7.K1 ; U7.D12 39.4,56.31 v2(39.73,56.63) ; v2(27.03,46.23) 26.7,46.56 U5.W12 ; U5.F3 19.35,55.01 v2(19.02,55.33) ; U5.B3 19.5,57.61 v2(19.82,57.28) ; U1.J14 v2(29.22,77.41) ; U5.K3 19.75,52.08 v2(19.82,52.08) ; U7.R1 30.45,49.16 v2(30.12,48.83) ; v2(26.63,77.41) U1.N14 ; v2(39.73,53.38) 39.4,53.71 U7.H12 ; v2(30.12,50.13) 30.45,50.46 U7.N1 ; v2(25.43,47.53) 25.1,47.86 U5.U10 ; U7.D5 34.05,56.63 v2(34.12,56.63) ; U7.AB4 32.85,44.61 v2(32.52,44.28) ; v2(21.42,57.93) 21.35,57.93 U5.B5 ; U5.AB4 20.15,44.61 v2(19.82,44.28) ; U5.N1 17.75,50.46 v2(17.42,50.13) ; v2(27.03,53.38) 26.7,53.71 U5.H12 ; U7.W1 30.45,46.56 v2(30.12,46.23) ; v2(27.03,50.13) 26.7,50.46 U5.N12 ; v2(23.83,56.63) 23.5,56.31 U5.D8 ; U7.B8 35.8,57.93 v2(35.73,57.93) ; U1.H14 v2(29.87,77.41) ; v2(23.83,46.23) 23.5,46.56 U5.W8 ; v2(37.33,44.28) 37,44.61 U7.AB9 ; U5.H1 17.75,53.71 v2(17.42,54.03) ; U7.B10 38.05,57.93 v2(38.13,57.93) ; U7.U3 32.05,47.86 v2(31.72,47.53) ; v2(30.12,54.03) 30.45,53.71 U7.H1 ; v2(17.42,48.83) 17.75,49.16 U5.R1 ; U5.N10 24.7,50.13 v2(24.63,50.13) ; v2(34.12,46.88) 34.05,46.88 U7.W5 ; v2(23.83,47.53) 23.5,47.86 U5.U8 ; v2(23.83,58.58) 23.9,58.58 U5.A9 ; v2(39.73,48.83) 39.4,49.16 U7.R12 ; v2(37.33,50.13) 37.4,50.13 U7.N10 ; U7.D1 30.45,56.31 v2(30.12,56.63) ; v2(36.53,47.53) 36.2,47.86 U7.U8 ; U7.A4 32.6,58.58 v2(32.52,58.58) ; v2(39.73,50.13) 39.4,50.46 U7.N12 ; U5.B10 25.1,57.61 v2(25.43,57.93) ; U5.AB9 24.3,44.61 v2(24.63,44.28) ; U5.AA10 25.1,45.26 v2(25.43,44.93) ; U7.F8 36.05,55.01 v2(35.73,55.33) ; U5.F10 25.1,55.01 v2(25.43,54.68) ; v2(36.53,49.48) 36.2,49.16 U7.R8 ; U7.AA5 33.65,45.26 v2(33.32,44.93) ; v2(38.13,44.93) 37.8,45.26 U7.AA10 ; v2(36.53,46.23) 36.2,46.56 U7.W8 ; U7.AA3 32.05,45.26 v2(31.72,44.93) ; v2(21.42,47.53) 21.35,47.53 U5.U5 ; v2(19.82,57.93) 20.15,58.26 U5.A4 ; U5.AA3 19.35,45.26 v2(19.02,44.93) ; U7.K12 39,52.08 v2(38.93,52.08) ; v2(17.42,46.23) 17.75,46.56 U5.W1 ; U7.N3 32.45,50.13 v2(32.52,50.13) ; v2(24.63,52.08) 24.7,52.08 U5.K10 ; U7.K10 37.4,52.08 v2(37.33,52.08) ; v2(35.73,55.98) 36.05,56.31 U7.D8 ; v2(31.72,57.93) 31.8,57.93 U7.B3 ; U5.N3 19.75,50.13 v2(19.82,50.13) ; v2(23.83,49.48) 23.5,49.16 U5.R8 ; v2(18.22,52.08) 18.15,52.08 U5.K1 ; v2(27.28,77.41) U1.M14 ; v2(35.73,54.03) 35.8,54.03 U7.H8
  BOTTOM w0.254: v2(17.42,54.03) 17.27,53.88 R63.2 ; C74.1 28.14,77.19 v2(27.93,77.41) ; C263.1 18.29,52.02 v2(18.22,52.08)
  BOTTOM w0.305: v2(34.12,57.93) 34.4,57.66 R69.2 ; R66.2 21.7,57.66 v2(21.42,57.93) ; C72.1 v1(30.86,70.99) R57.1 C62.2
  vias: v1(20.75,68.63) v1(20.75,67.61) v1(34.29,42.55) v1(34.29,41.27) v1(35.56,42.55) v1(35.56,41.27) v1(36.83,42.55) v1(36.83,41.27) v1(38.1,42.55) v1(38.1,41.27) v2(22.23,47.53) v2(23.03,47.53) v2(26.63,74.81) v2(34.92,47.53) v2(35.73,47.53)
DDR_VREF: length 0.5
  TOP w0.203: U1.K17 v2(28.58,75.46)
DEBUG_DM: length 10.6
  TOP w0.114: J6.A7 71.58,104.41 ; 71.58,104.41 71.42,104.57 70.08,104.57 66.84,107.81 66.04,107.81 65.96,107.73 U26.7 ; 71.58,104.41 71.34,104.17 71.34,103.72 71.65,103.41 J6.B7
DEBUG_DP: length 11.5
  TOP w0.114: J6.A6 73.38,103.91 73.5,104.02 73.5,104.8 73.38,104.91 J6.B6 70.22,104.91 66.98,108.15 66.04,108.15 65.96,108.23 U26.8
DL_M_CLK2: length 107.5
  TOP w0.127: v3(40.25,131.57) J3.31 ; v1(6.35,79.63) R116.2
  ART06 w0.127: v1(6.35,79.63) 6.72,80 6.72,84.73 8.14,86.16 10.68,86.16 20.32,95.8 20.32,117.98 32.89,130.56 39.24,130.56 v3(40.25,131.57)
  BOTTOM w0.127: v3(40.25,131.57) 39.75,132.08 39.75,133.73 38.48,135 12.32,135 J17.1
DL_M_CLK3: length 92.2
  TOP w0.127: v1(1.65,81.03) 3.17,79.5 3.17,76.83 3.81,76.2 5.08,76.2 5.59,75.69 5.59,69.85 6.1,69.34 R118.2 ; J3.35 41.26,131.21 40.77,131.7 40.77,132.08 v3(40.26,132.59)
  ART06 w0.127: v3(40.26,132.59) 39.88,132.59 39.37,132.08 32.14,132.08 18.67,118.61 18.67,96.32 10.11,87.76 6.48,87.76 1.65,82.93 v1(1.65,81.03)
DMI0_A: length 32.7
  TOP w0.086: v2(19.82,56.63) 19.5,56.96 U5.C3 ; U1.V17 v2(23.38,75.46)
  ART06 w0.086: v2(19.82,56.63) 19.82,56.78 19.48,57.12 19.48,59.13 18.47,60.15 17.17,60.15 16.43,60.88 16.43,60.89 16.29,61.03 16.29,61.23 16.43,61.37 16.43,61.57 16.29,61.71 16.09,61.71 15.95,61.57 15.75,61.57 15.47,61.85 15.47,62.1 15.6,62.23 16.38,62.23 16.49,62.35 16.49,62.52 16.63,62.66 16.83,62.66 16.97,62.52 16.97,62.35 17.11,62.2 17.31,62.2 17.45,62.35 17.45,63.49 17.59,63.63 17.79,63.63 17.93,63.49 17.93,62.68 18.05,62.56 18.29,62.56 18.41,62.69 18.41,67.56 18.22,67.76 18.22,67.96 18.35,68.09 18.35,68.29 18.21,68.43 18.01,68.43 17.88,68.3 17.68,68.3 16.99,68.99 16.99,70.13 19.76,72.9 20.32,72.9 22.23,74.8 22.52,74.8 23.17,75.46 v2(23.38,75.46)
DMI0_B: length 32.4
  TOP w0.086: U7.C3 31.8,57.28 v2(31.72,57.28) ; v2(33.12,74.81) U1.D18
  ART06 w0.086: v2(31.72,57.28) 31.49,57.28 31.34,57.43 31.34,58.17 31.2,58.31 30.32,58.31 30.18,58.45 30.18,58.65 30.32,58.79 31.2,58.79 31.34,58.93 31.34,59.13 31.2,59.27 30.32,59.27 30.18,59.41 30.18,59.61 30.32,59.75 31.28,59.75 31.37,59.84 31.37,60.12 31.26,60.23 30.32,60.23 30.18,60.37 30.18,60.57 30.32,60.71 31.28,60.71 31.39,60.83 31.39,63.46 31.48,63.55 32.16,63.55 32.3,63.69 32.3,63.89 32.16,64.03 31.42,64.03 31.29,64.16 31.29,64.39 31.42,64.51 32.14,64.51 32.28,64.65 32.28,64.85 32.14,64.99 31.48,64.99 31.34,65.13 31.34,69.19 31.22,69.32 30.99,69.32 30.86,69.19 30.86,68.79 30.75,68.68 30.49,68.68 30.38,68.79 30.38,72.04 30.46,72.12 32.12,72.12 32.26,72.26 32.26,72.47 32.8,73.01 32.8,74.71 32.9,74.81 v2(33.12,74.81)
DMI1_A: length 32.2
  TOP w0.086: v2(25.43,57.28) 25.1,56.96 U5.C10 ; U1.P17 v2(26.63,75.46)
  ART06 w0.086: v2(26.63,75.46) 27.95,74.13 27.95,69.94 28.27,69.62 28.27,54.23 27.94,53.9 27.94,52.15 27.84,52.04 27.56,52.04 27.46,52.14 27.46,53.77 27.36,53.87 26.71,53.87 26.62,53.96 26.62,56.06 26.37,56.31 26.09,56.31 25.78,56.62 25.78,56.93 v2(25.43,57.28)
DMI1_B: length 33.7
  TOP w0.086: v2(38.13,57.28) 38.05,57.28 U7.C10 ; U1.C15 v2(33.78,77.41)
  ART06 w0.086: v2(33.78,77.41) 33.96,77.41 34.29,77.74 35.17,77.74 35.43,77.47 37.07,77.47 42.9,71.64 42.9,69.04 42.77,68.91 41.48,68.91 39.83,67.26 39.83,64.82 41.38,63.27 42.44,63.27 42.9,62.81 42.9,61.34 39.83,58.27 38.71,58.27 38.48,58.04 38.48,57.64 v2(38.13,57.28)
DP_M_CLK1: length 79.4
  TOP w0.127: R89.1 6.22,76.2 5.59,76.83 5.59,77.98 v1(4.45,79.12) ; J3.26 v3(38.75,131.57)
  ART06 w0.127: v1(4.45,79.12) 4.45,83.99 5.59,85.13 5.59,86.11 6.65,87.17 10.25,87.17 19.3,96.23 19.3,118.53 32.35,131.57 v3(38.75,131.57)
DP_RST: length 6.2
  TOP w0.127: J3.44 43.26,135.06 v3(43.31,135.12)
  BOTTOM w0.127: R179.1 44.45,131.31 44.45,133.97 v3(43.31,135.12)
DP_STROBE: length 6.6
  TOP w0.127: J3.50 44.76,134.8 45.08,135.12 v3(45.71,135.12)
  BOTTOM w0.127: R181.1 46.48,134.35 v3(45.71,135.12)
DP_VSYNC: length 5.9
  TOP w0.127: J3.48 v3(44.26,135.12)
  BOTTOM w0.127: v3(44.26,135.12) 45.21,134.16 R180.1
DQ_A0: length 33.6
  TOP w0.086: U5.B2 18.3,57.93 v2(17.42,57.93) ; U1.U16 v2(24.03,76.11)
  ART06 w0.086: v2(24.03,76.11) 24.03,76.34 23.94,76.43 20.83,76.43 20.7,76.3 20.7,75.79 20.17,75.26 18.87,75.26 11.11,67.5 11.11,62.95 11.93,62.14 12.13,62.14 12.35,62.36 12.55,62.36 12.69,62.22 12.69,62.02 12.47,61.8 12.47,61.6 16.13,57.93 16.47,57.93 16.61,57.79 16.61,57.49 16.75,57.35 16.95,57.35 17.09,57.49 17.09,57.79 17.23,57.93 v2(17.42,57.93)
DQ_A1: length 33.4
  TOP w0.086: U5.C2 18.55,56.96 v2(18.22,57.28) ; U1.T16 v2(24.68,76.11)
  ART06 w0.086: v2(18.22,57.28) 18.22,58.25 17.83,58.65 16.46,58.65 13.72,61.39 13.72,62.99 13.38,63.33 13.18,63.33 13,63.15 12.8,63.15 12.66,63.29 12.66,63.49 12.84,63.67 12.84,63.87 12.7,64.01 12.5,64.01 12.32,63.83 12.12,63.83 11.98,63.97 11.98,64.17 12.16,64.35 12.16,64.55 11.82,64.88 11.82,67.2 13.64,69.02 13.84,69.02 14.05,68.81 14.25,68.81 14.39,68.95 14.39,69.15 14.18,69.36 14.18,69.55 19.18,74.55 20.36,74.55 21.6,75.79 24.59,75.79 24.68,75.88 v2(24.68,76.11)
DQ_A2: length 32.4
  TOP w0.086: v2(18.22,55.98) 18.55,55.66 U5.E2 ; U1.V16 v2(23.38,76.11)
  ART06 w0.086: v2(23.38,76.11) 21.47,76.11 20.27,74.9 19.02,74.9 11.47,67.35 11.47,63.94 11.78,63.64 11.78,63.44 11.56,63.22 11.56,63.02 11.7,62.88 11.9,62.88 12.12,63.1 12.32,63.1 13.31,62.1 13.31,61.29 16.31,58.29 17.7,58.29 17.83,58.17 17.83,56.38 v2(18.22,55.98)
DQ_A3: length 31.2
  TOP w0.086: U1.Y16 21.9,76.44 21.41,75.95 v2(20.33,75.95) ; v2(18.22,55.33) 18.55,55.01 U5.F2
  ART06 w0.086: v2(18.22,55.33) 10.76,62.8 10.76,67.65 18.72,75.62 20,75.62 v2(20.33,75.95)
DQ_A4: length 31.4
  TOP w0.086: v2(19.82,55.33) 20.15,55.01 U5.F4 ; U1.W18 v2(23.38,74.81)
  ART06 w0.086: v2(19.82,55.33) 19.46,54.97 19.46,51.77 19.58,51.64 20.19,51.64 20.31,51.75 20.31,55.57 20.41,55.66 20.97,55.66 21.08,55.78 21.08,59.11 20.4,59.79 20.4,64.36 19.91,64.85 19.91,71.04 22.67,73.8 22.82,73.8 23.05,74.03 23.05,74.49 v2(23.38,74.81)
DQ_A5: length 31.7
  TOP w0.086: U5.E4 20.3,55.66 v2(20.62,55.33) ; U1.V18 v2(24.03,74.81)
  ART06 w0.086: v2(24.03,74.81) 23.83,74.81 23.37,74.35 23.37,73.99 20.27,70.89 20.27,67.31 20.41,67.17 20.56,67.17 20.7,67.03 20.7,66.83 20.56,66.69 20.41,66.69 20.27,66.55 20.27,65 20.75,64.52 20.75,59.97 21.74,58.98 21.74,51.65 21.66,51.56 21.04,51.56 20.95,51.65 20.95,55 v2(20.62,55.33)
DQ_A6: length 30.2
  TOP w0.086: v2(20.62,56.63) 20.3,56.96 U5.C4 ; v2(22.08,74.16) 22.08,74.81 U1.Y18
  ART06 w0.086: v2(22.08,74.16) 20.27,72.36 20.07,72.36 20,72.43 19.8,72.43 18.98,71.61 18.98,71.41 19.05,71.34 19.05,71.13 18.91,70.99 18.43,70.99 18.29,70.85 18.29,70.65 18.43,70.51 19.07,70.51 19.2,70.38 19.2,69.13 18.77,68.69 18.77,61.16 18.62,61.01 18.39,61.01 18.26,61.14 18.26,62.08 18.14,62.2 17.9,62.2 17.76,62.06 17.76,61.23 17.61,61.09 17.42,61.09 17.28,61.23 17.28,61.71 17.13,61.85 16.89,61.85 16.79,61.75 16.79,61.04 17.32,60.5 18.62,60.5 20.19,58.93 20.19,56.77 20.33,56.63 v2(20.62,56.63)
DQ_A7: length 31.9
  TOP w0.086: U5.B4 20.3,57.61 v2(20.62,57.28) ; v2(24.03,75.46) 24.35,75.78 U1.U17
  ART06 w0.086: v2(20.62,57.28) 20.62,59.03 20.26,59.4 19.85,59.8 19.85,60 20,60.14 20,60.34 19.86,60.48 19.66,60.48 19.51,60.34 19.31,60.34 18.97,60.68 18.97,60.86 19.1,60.98 19.95,60.98 20.04,61.07 20.04,61.37 19.94,61.47 19.24,61.47 19.13,61.58 19.13,61.8 19.27,61.94 19.95,61.94 20.04,62.03 20.04,62.28 19.9,62.42 19.27,62.42 19.13,62.57 19.13,62.76 19.27,62.9 19.9,62.9 20.04,63.05 20.04,63.24 19.9,63.38 19.27,63.38 19.13,63.53 19.13,63.72 19.27,63.86 19.9,63.86 20.04,64.01 20.04,64.2 19.9,64.34 19.27,64.34 19.13,64.49 19.13,64.68 19.27,64.82 19.42,64.82 19.56,64.97 19.56,65.16 19.42,65.3 19.27,65.3 19.13,65.45 19.13,65.64 19.27,65.78 19.42,65.78 19.56,65.93 19.56,66.12 19.42,66.27 19.27,66.27 19.13,66.41 19.13,66.6 19.27,66.75 19.42,66.75 19.56,66.89 19.56,67.08 19.42,67.23 19.27,67.23 19.13,67.37 19.13,67.56 19.27,67.71 19.42,67.71 19.56,67.85 19.56,68.04 19.42,68.19 19.27,68.19 19.13,68.33 19.13,68.55 19.25,68.68 19.46,68.68 19.56,68.78 19.56,71.37 19.49,71.44 19.49,71.61 19.66,71.78 19.83,71.78 19.93,71.68 20.07,71.68 22.4,74.02 22.4,74.3 23.24,75.13 23.94,75.13 24.03,75.22 v2(24.03,75.46)
DQ_A8: length 32.2
  TOP w0.086: v2(26.23,57.93) 25.9,57.61 U5.B11 ; U1.R17 v2(25.33,76.11)
  ART06 w0.086: v2(25.33,76.11) 25.57,76.11 25.65,76.02 25.65,75.9 25.48,75.72 25.48,75.48 25.65,75.3 25.65,73.95 25.77,73.84 26.11,73.84 26.3,73.65 26.3,73.34 26.01,73.05 26.01,65.91 26.15,65.77 27.06,65.77 27.2,65.63 27.2,65.43 27.06,65.29 26.15,65.29 26.01,65.15 26.01,64.95 26.15,64.81 27.06,64.81 27.2,64.67 27.2,64.47 27.06,64.33 26.15,64.33 26.01,64.19 26.01,63.99 26.15,63.85 27.06,63.85 27.2,63.71 27.2,63.51 27.06,63.37 26.15,63.37 26.01,63.23 26.01,63.03 26.15,62.89 27.06,62.89 27.2,62.75 27.2,62.55 27.06,62.41 26.11,62.41 26.01,62.31 26.01,61.98 26.14,61.85 27.07,61.85 27.2,61.71 27.2,57.72 27.12,57.63 26.81,57.63 26.72,57.72 26.72,58.48 26.6,58.6 26.34,58.6 26.23,58.48 v2(26.23,57.93)
DQ_A9: length 30.4
  TOP w0.086: v2(26.23,57.28) 25.9,56.96 U5.C11 ; v2(25.98,74.81) 25.33,74.81 U1.T18
  ART06 w0.086: v2(25.98,74.81) 25.98,74.62 26.3,74.3 26.3,74.03 26.49,73.84 26.76,73.84 26.95,73.65 26.95,73.26 26.86,73.18 26.67,73.18 26.37,72.87 26.37,69.23 26.51,69.09 26.91,69.09 27.05,68.95 27.05,68.75 26.91,68.61 26.51,68.61 26.37,68.47 26.37,68.29 26.51,68.15 27.42,68.15 27.56,68.01 27.56,67.81 27.42,67.67 26.51,67.67 26.37,67.53 26.37,67.33 26.51,67.19 27.42,67.19 27.56,67.05 27.56,66.85 27.42,66.71 26.51,66.71 26.37,66.57 26.37,66.37 26.51,66.23 27.42,66.23 27.56,66.09 27.56,55.81 27.42,55.68 27.19,55.68 27.05,55.81 27.05,56.13 26.67,56.52 26.67,57.18 26.56,57.28 v2(26.23,57.28)
DQ_A10: length 31.8
  TOP w0.086: v2(27.03,55.33) 26.15,55.33 U5.E11 ; U1.R18 v2(25.98,75.46)
  ART06 w0.086: v2(27.03,55.33) 27.22,55.33 27.43,55.12 27.43,54.69 27.53,54.58 27.83,54.58 27.91,54.67 27.91,68.35 27.77,68.49 27.55,68.49 27.41,68.63 27.41,68.83 27.55,68.97 27.82,68.97 27.91,69.06 27.91,69.34 27.81,69.44 26.87,69.44 26.77,69.55 26.77,69.82 26.89,69.94 27.44,69.94 27.58,70.08 27.58,70.28 27.44,70.42 26.89,70.42 26.75,70.56 26.75,70.76 26.89,70.9 27.44,70.9 27.58,71.04 27.58,71.24 27.44,71.38 26.89,71.38 26.75,71.52 26.75,71.72 26.89,71.86 27.44,71.86 27.58,72 27.58,72.2 27.44,72.34 26.89,72.34 26.77,72.45 26.77,72.72 26.87,72.82 27.48,72.82 27.6,72.94 27.6,73.72 27.48,73.84 27.13,73.84 26.95,74.02 26.95,74.4 26.86,74.49 26.48,74.49 26.3,74.67 26.3,75.37 26.21,75.46 v2(25.98,75.46)
DQ_A11: length 30.5
  TOP w0.086: U1.U20 v2(24.68,73.51) ; v2(24.63,55.33) 25.5,55.33 U5.F11
  ART06 w0.086: v2(24.63,55.33) 24.99,54.97 24.99,51.99 25.12,51.87 26.46,51.87 26.54,51.95 26.54,52.24 26.46,52.32 26.01,52.32 25.88,52.45 25.88,56.01 24.93,56.96 24.45,56.96 24.26,57.15 24.26,58.6 24.08,58.78 24.08,70.1 24.94,70.97 24.94,72.47 24.68,72.73 v2(24.68,73.51)
DQ_A12: length 29.4
  TOP w0.086: U1.W19 23.38,74.16 23.38,73.41 v2(22.86,72.9) ; v2(24.63,54.68) 24.3,55.01 U5.F9
  ART06 w0.086: v2(24.63,54.68) 24.23,54.29 24.23,51.92 24,51.69 22.83,51.69 22.24,52.28 22.24,59.19 21.23,60.2 21.23,71.17 22.86,72.8 v2(22.86,72.9)
DQ_A13: length 31.2
  TOP w0.086: U5.E9 24.15,55.66 v2(23.83,55.33) ; U1.U18 v2(24.68,74.81)
  ART06 w0.086: v2(24.68,74.81) 24.68,74.57 24.59,74.49 23.88,74.49 23.65,74.26 23.65,73.81 23.23,73.39 23.23,72.66 23.39,72.49 23.39,72 23.19,71.79 22.93,71.79 22.74,71.98 22.54,71.98 21.59,71.03 21.59,60.38 21.73,60.23 21.96,60.23 22.2,60.48 22.4,60.48 22.54,60.34 22.54,60.14 22.3,59.9 22.3,59.67 22.61,59.36 22.61,52.5 22.69,52.41 23.33,52.41 23.42,52.5 23.42,55.25 23.51,55.33 v2(23.83,55.33)
DQ_A14: length 34.3
  TOP w0.086: U5.C9 24.3,56.96 v2(24.63,57.28) ; v2(25.98,76.11) U1.P16
  ART06 w0.086: v2(24.63,57.28) 24.96,57.62 25.76,57.62 25.84,57.7 25.84,58.41 25.75,58.5 25.52,58.5 25.4,58.62 25.4,58.87 25.52,58.98 26.72,58.98 26.85,59.11 26.85,59.41 26.7,59.56 24.93,59.56 24.79,59.7 24.79,59.89 24.93,60.04 26.71,60.04 26.85,60.18 26.85,60.38 26.71,60.52 24.93,60.52 24.79,60.66 24.79,60.86 24.93,61 26.71,61 26.85,61.14 26.85,61.34 26.71,61.48 24.93,61.48 24.79,61.62 24.79,61.82 24.93,61.96 25.51,61.96 25.65,62.1 25.65,73.63 25.27,74.02 25.27,75.17 25.01,75.44 25.01,76.27 25.16,76.43 25.86,76.43 25.98,76.32 v2(25.98,76.11)
DQ_A15: length 31.6
  TOP w0.086: U1.T17 v2(24.68,75.46) ; v2(24.63,57.93) 24.3,57.61 U5.B9
  ART06 w0.086: v2(24.68,75.46) 24.68,75.27 25.01,74.94 25.01,72.91 25.3,72.62 25.3,70.16 25.21,70.08 24.56,70.08 24.43,69.95 24.43,69.61 24.52,69.52 25.16,69.52 25.3,69.38 25.3,69.18 25.16,69.04 24.54,69.04 24.43,68.94 24.43,68.66 24.53,68.56 25.21,68.56 25.3,68.48 25.3,68.17 25.21,68.08 24.58,68.08 24.43,67.94 24.43,67.74 24.58,67.6 25.16,67.6 25.3,67.46 25.3,67.26 25.16,67.12 24.58,67.12 24.43,66.98 24.43,66.78 24.58,66.64 25.16,66.64 25.3,66.5 25.3,66.3 25.16,66.16 24.58,66.16 24.43,66.02 24.43,65.82 24.58,65.68 25.16,65.68 25.3,65.54 25.3,65.34 25.16,65.2 24.58,65.2 24.43,65.06 24.43,64.86 24.58,64.72 25.16,64.72 25.3,64.58 25.3,64.38 25.16,64.24 24.58,64.24 24.43,64.1 24.43,63.9 24.58,63.76 25.16,63.76 25.3,63.62 25.3,63.42 25.16,63.28 24.58,63.28 24.43,63.14 24.43,62.94 24.58,62.8 25.16,62.8 25.3,62.66 25.3,62.46 25.16,62.32 24.58,62.32 24.43,62.18 24.43,59.05 24.54,58.95 24.93,58.95 25.02,58.87 25.02,58.04 24.91,57.93 v2(24.63,57.93)
DQ_B0: length 33.5
  TOP w0.086: v2(30.92,57.93) 31.25,57.61 U7.B2 ; v2(32.48,75.46) U1.D17
  ART06 w0.086: v2(30.92,57.93) 29.91,57.93 29.82,58.02 29.82,60.93 29.96,61.07 30.9,61.07 31.04,61.22 31.04,61.41 30.9,61.55 29.96,61.55 29.82,61.7 29.82,61.91 29.96,62.05 30.9,62.05 31.04,62.2 31.04,62.39 30.9,62.53 29.96,62.53 29.82,62.68 29.82,62.87 29.96,63.01 30.9,63.01 31.04,63.16 31.04,63.35 30.9,63.49 29.96,63.49 29.82,63.64 29.82,63.83 29.96,63.97 30.8,63.97 30.94,64.12 30.94,64.31 30.8,64.45 29.96,64.45 29.82,64.6 29.82,64.79 29.96,64.93 30.85,64.93 30.99,65.08 30.99,68.15 30.85,68.3 30.03,68.3 29.84,68.48 29.84,68.86 30.02,69.04 30.02,69.34 29.84,69.52 29.84,69.82 30.02,70 30.02,70.67 29.88,70.81 29.66,70.81 29.51,70.95 29.51,71.15 29.66,71.29 29.88,71.29 30.02,71.43 30.02,71.63 29.88,71.77 29.66,71.77 29.51,71.91 29.51,72.34 29.66,72.48 31.76,72.48 32.48,73.19 v2(32.48,75.46)
DQ_B1: length 34
  TOP w0.086: U1.D16 33.12,76.11 v2(33.13,76.11) ; U7.C2 31.25,56.96 v2(30.92,57.28)
  ART06 w0.086: v2(30.92,57.28) 31.32,56.89 31.32,56.44 31.19,56.31 29.59,56.31 29.46,56.44 29.46,56.58 29.6,56.72 29.7,56.72 29.84,56.86 29.84,57.06 29.7,57.2 29.6,57.2 29.46,57.34 29.46,65.32 29.6,65.46 30.49,65.46 30.63,65.61 30.63,65.8 30.49,65.95 29.6,65.95 29.46,66.09 29.46,66.28 29.6,66.43 30.49,66.43 30.63,66.57 30.63,66.76 30.49,66.91 29.6,66.91 29.46,67.05 29.46,67.24 29.6,67.39 30.49,67.39 30.63,67.53 30.63,67.72 30.49,67.87 29.6,67.87 29.46,68.01 29.46,70.38 29.16,70.69 29.16,72.64 29.35,72.83 30.92,72.83 31.11,73.03 31.31,73.03 31.5,72.83 31.61,72.83 32.15,73.37 32.15,76.02 32.45,76.33 32.91,76.33 v2(33.13,76.11)
DQ_B2: length 33.9
  TOP w0.086: U7.E2 31.25,55.66 v2(30.92,55.98) ; v2(31.83,74.81) U1.E18
  ART06 w0.086: v2(31.83,74.81) 31.5,75.13 30.95,75.13 30.85,75.03 30.85,73.37 30.67,73.19 29.22,73.19 28.8,72.77 28.8,70.54 29.11,70.23 29.11,56.1 29.25,55.96 29.55,55.96 29.69,55.82 29.69,55.62 29.55,55.48 29.25,55.48 29.11,55.34 29.11,55.14 29.25,55 29.55,55 29.69,54.86 29.69,54.66 29.55,54.52 29.25,54.52 29.11,54.38 29.11,54.18 29.25,54.04 29.55,54.04 29.69,53.9 29.69,53.7 29.55,53.56 29.25,53.56 29.11,53.42 29.11,52.64 29.19,52.55 30.43,52.55 30.51,52.64 30.51,55.58 v2(30.92,55.98)
DQ_B3: length 33.6
  TOP w0.086: v2(30.92,55.33) 31.25,55.01 U7.F2 ; v2(31.83,75.46) U1.E17
  ART06 w0.086: v2(30.92,55.33) 31.29,54.97 31.29,51.78 31.21,51.69 28.84,51.69 28.75,51.78 28.75,70.08 28.45,70.38 28.45,72.92 29.67,74.14 29.67,74.63 30.82,75.78 31.5,75.78 v2(31.83,75.46)
DQ_B4: length 33.7
  TOP w0.086: U1.C17 v2(33.13,75.46) ; v2(33.32,55.33) 33,55.01 U7.F4
  ART06 w0.086: v2(33.13,75.46) 33.13,75.22 33.21,75.13 34.59,75.13 35.99,73.74 35.99,68.02 36.35,67.67 36.35,67.45 36.07,67.17 36.07,66.97 36.35,66.69 36.35,61.93 34.54,60.12 34.54,54.28 34.46,54.2 33.8,54.2 33.66,54.06 33.66,53.86 33.8,53.72 34.42,53.72 34.57,53.57 34.57,52.96 34.44,52.83 34.13,52.83 33.88,53.09 33.65,53.09 33.4,52.83 33.07,52.83 32.92,52.98 32.92,54.23 33.06,54.38 33.39,54.38 33.53,54.52 33.53,54.71 33.39,54.86 33.06,54.86 32.92,55 32.92,55.25 33,55.33 v2(33.32,55.33)
DQ_B5: length 32.1
  TOP w0.086: U7.E4 32.85,55.66 v2(32.52,55.33) ; U1.C18 v2(33.78,75.46)
  ART06 w0.086: v2(32.52,55.33) 32.13,54.94 32.13,52.58 32.3,52.41 34.71,52.41 34.92,52.63 34.92,60 36.7,61.77 36.7,67.82 36.35,68.17 36.35,73.74 34.62,75.46 v2(33.78,75.46)
